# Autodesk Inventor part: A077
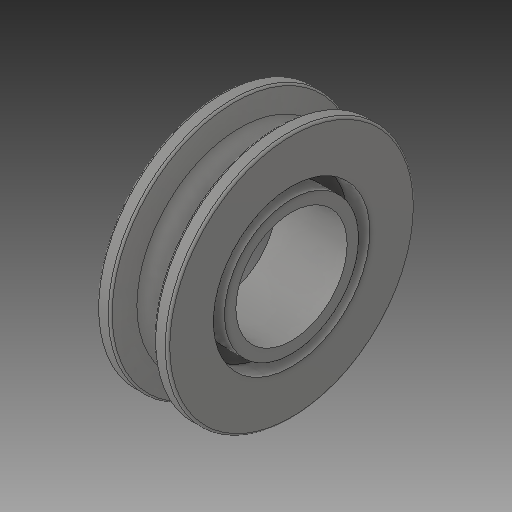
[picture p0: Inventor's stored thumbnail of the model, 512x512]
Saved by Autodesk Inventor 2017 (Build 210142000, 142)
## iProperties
Created: 2012-03
Part Number: A077
Material: Générique
Document SubType Name: Modeling
Designer: ficho
Density: 1 g/cm^3
Appearance: Par défaut
Title: C:\# CARLOS\MECANO\mecano-Componentes\A077.stp
Author: cv
Sending System: Autodesk Inventor 2012
Preprocessor: Autodesk Inventor 2012
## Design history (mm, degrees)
feature "Solid1"
node "Solide1"
